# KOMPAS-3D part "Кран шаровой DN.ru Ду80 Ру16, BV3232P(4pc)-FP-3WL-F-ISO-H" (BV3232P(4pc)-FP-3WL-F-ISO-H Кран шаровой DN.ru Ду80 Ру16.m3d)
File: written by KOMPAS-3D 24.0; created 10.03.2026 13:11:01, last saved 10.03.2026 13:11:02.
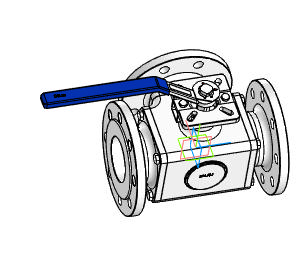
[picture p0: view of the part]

Document properties: Автор: R2D2; Полное имя файла: BV3232P(4pc)-FP-3WL-F-ISO-H Кран шаровой DN.ru Ду80 Ру16.cdw

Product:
- Part/product: Кран шаровой DN.ru Ду80 Ру16  | designation BV3232P(4pc)-FP-3WL-F-ISO-H
    Масса: 39.1
    Раздел спецификации: Прочие изделия
    Форматы листов документа: A2
    Примечание: D160-36362

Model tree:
1. Операция без истории:1

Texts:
  BV3232P(4pc)-FP-3WL-F-ISO-H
